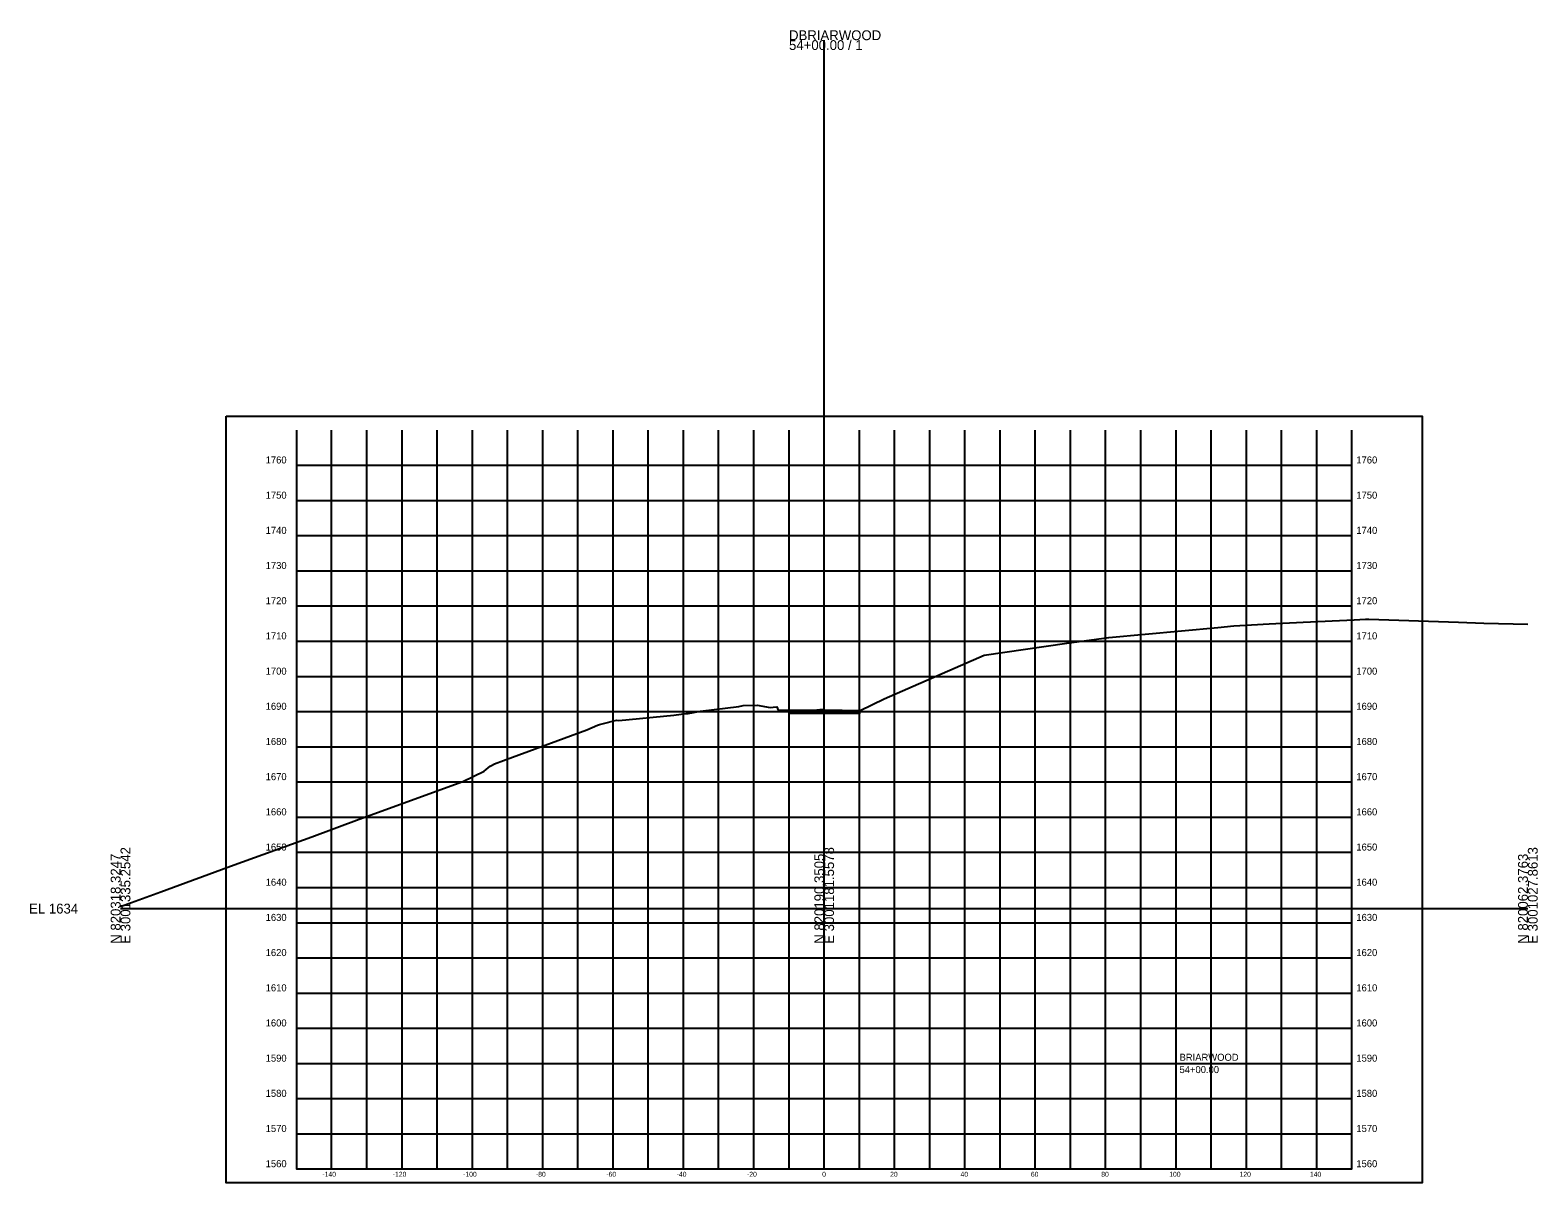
# Model space of a CAD drawing. Extents: x 74 to 503, y -54 to 3770.
# Drawn here: x 74.3 to 502.8, y 3442.1 to 3769.7 of the extents above; entities that cross this region are included whole.
import ezdxf

# ---------------------------------------------------------------- set-up
doc = ezdxf.new("R2010")
doc.units = 0
for name, color, linetype in [('DESIGN - EARTHWORK - Shapes', 7, 'Continuous'), ('DESIGN - SHEET - Corner Text', 7, 'Continuous'), ('DESIGN - SHEET - Light Grid', 7, 'Continuous'), ('DESIGN - SHEET - Linework', 7, 'Continuous'), ('DESIGN - SHEET - Plot Shape', 7, 'Continuous'), ('DESIGN - TYPICAL - Warning Text', 7, 'Continuous'), ('SURVEY - GROUND - Top of Ground', 7, 'Continuous')]:
    doc.layers.add(name, color=color, linetype=linetype)

msp = doc.modelspace()

# ---------------------------------------------------------------- linework, layer by layer
at = {"layer": 'DESIGN - EARTHWORK - Shapes'}
for points in [[(290, 3575.39), (290, 3576.39), (297.87, 3576.47), (298.74, 3576.48), (300, 3576.46), (310, 3576.32), (310, 3575.32), (300, 3575.46)], [(290, 3575.39), (290, 3576.39), (297.87, 3576.47), (298.74, 3576.48), (300, 3576.46), (310, 3576.32), (310, 3575.32), (300, 3575.46)], [(297.87, 3576.47), (298.74, 3576.48), (299.55, 3576.47), (300, 3576.46), (310, 3576.32), (310, 3575.32), (300, 3575.46), (290, 3575.39), (290, 3576.39)], [(298.74, 3576.48), (300, 3576.46), (299.55, 3576.47)], [(298.74, 3576.48), (300, 3576.46), (299.55, 3576.47)]]:
    msp.add_lwpolyline(points, close=True, dxfattribs=at)
at = {"layer": 'DESIGN - SHEET - Light Grid'}
for p, q in [((300, 3520), (300, 3766.81)), ((100, 3520), (300, 3520)), ((300, 3520), (500, 3520))]:
    msp.add_line(p, q, dxfattribs=at)
at = {"layer": 'DESIGN - SHEET - Linework'}
for p, q in [((160, 3446), (160, 3656)), ((170, 3446), (170, 3656)), ((180, 3446), (180, 3656)), ((190, 3446), (190, 3656)), ((200, 3446), (200, 3656)), ((210, 3446), (210, 3656)), ((220, 3446), (220, 3656)), ((230, 3446), (230, 3656)), ((240, 3446), (240, 3656)), ((250, 3446), (250, 3656)), ((260, 3446), (260, 3656)), ((270, 3446), (270, 3656)), ((280, 3446), (280, 3656)), ((290, 3446), (290, 3656)), ((300, 3446), (300, 3656)), ((310, 3446), (310, 3656)), ((320, 3446), (320, 3656)), ((330, 3446), (330, 3656)), ((340, 3446), (340, 3656)), ((350, 3446), (350, 3656)), ((360, 3446), (360, 3656)), ((370, 3446), (370, 3656)), ((380, 3446), (380, 3656)), ((390, 3446), (390, 3656)), ((400, 3446), (400, 3656)), ((410, 3446), (410, 3656)), ((420, 3446), (420, 3656)), ((430, 3446), (430, 3656)), ((440, 3446), (440, 3656)), ((150, 3646), (450, 3646)), ((150, 3636), (450, 3636)), ((150, 3626), (450, 3626)), ((150, 3616), (450, 3616)), ((150, 3606), (450, 3606)), ((150, 3596), (450, 3596)), ((150, 3586), (450, 3586)), ((150, 3576), (450, 3576)), ((150, 3566), (450, 3566)), ((150, 3556), (450, 3556)), ((150, 3546), (450, 3546)), ((150, 3536), (450, 3536)), ((150, 3526), (450, 3526)), ((150, 3516), (450, 3516)), ((150, 3506), (450, 3506)), ((150, 3496), (450, 3496)), ((150, 3486), (450, 3486)), ((150, 3476), (450, 3476)), ((150, 3466), (450, 3466)), ((150, 3456), (450, 3456))]:
    msp.add_line(p, q, dxfattribs=at)
msp.add_lwpolyline([(150, 3656), (150, 3446), (450, 3446), (450, 3656)], dxfattribs=at)
at = {"layer": 'DESIGN - SHEET - Plot Shape'}
msp.add_lwpolyline([(130, 3659.94), (470, 3659.94), (470, 3442.06), (130, 3442.06)], close=True, dxfattribs=at)
at = {"layer": 'SURVEY - GROUND - Top of Ground'}
msp.add_lwpolyline([(100, 3520.56), (111.49, 3524.81), (132.32, 3532.43), (154.41, 3540.44), (167.84, 3545.46), (197.33, 3556.12), (203.36, 3559.06), (205.06, 3560.5), (205.41, 3560.71), (206.25, 3561.1), (211.37, 3563.05), (232.5, 3570.84), (235.6, 3572.17), (236.14, 3572.32), (236.87, 3572.48), (240.97, 3573.51), (241.64, 3573.49), (257.25, 3575.02), (260.78, 3575.42), (261.37, 3575.45), (264.88, 3576.08), (275.7, 3577.42), (276.94, 3577.76), (280.9, 3577.86), (284.63, 3577.16), (285.49, 3577.22), (286.53, 3577.32), (286.96, 3576.37), (297.87, 3576.47), (298.74, 3576.48), (299.55, 3576.47), (300, 3576.46), (310.23, 3576.31), (317, 3579.66), (345.42, 3592.03), (368.99, 3595.47), (380.94, 3597.05), (411.9, 3599.93), (416.45, 3600.4), (426.44, 3600.96), (436.1, 3601.4), (450.64, 3602.08), (453.89, 3602.27), (454.83, 3602.21), (480.26, 3601.38), (487.49, 3601.14), (500, 3600.84)], dxfattribs=at)

# ---------------------------------------------------------------- texts
at = {"layer": 'DESIGN - SHEET - Corner Text'}
for s, height, p in [('1760', 2, (141.25, 3646.5)), ('1760', 2, (451.25, 3646.5)), ('1750', 2, (141.25, 3636.5)), ('1750', 2, (451.25, 3636.5)), ('1740', 2, (141.25, 3626.5)), ('1740', 2, (451.25, 3626.5)), ('1730', 2, (141.25, 3616.5)), ('1730', 2, (451.25, 3616.5)), ('1720', 2, (141.25, 3606.5)), ('1720', 2, (451.25, 3606.5)), ('1710', 2, (141.25, 3596.5)), ('1710', 2, (451.25, 3596.5)), ('1700', 2, (141.25, 3586.5)), ('1700', 2, (451.25, 3586.5)), ('1690', 2, (141.25, 3576.5)), ('1690', 2, (451.25, 3576.5)), ('1680', 2, (141.25, 3566.5)), ('1680', 2, (451.25, 3566.5)), ('1670', 2, (141.25, 3556.5)), ('1670', 2, (451.25, 3556.5)), ('1660', 2, (141.25, 3546.5)), ('1660', 2, (451.25, 3546.5)), ('1650', 2, (141.25, 3536.5)), ('1650', 2, (451.25, 3536.5)), ('1640', 2, (141.25, 3526.5)), ('1640', 2, (451.25, 3526.5)), ('1630', 2, (141.25, 3516.5)), ('1630', 2, (451.25, 3516.5)), ('1620', 2, (141.25, 3506.5)), ('1620', 2, (451.25, 3506.5)), ('1610', 2, (141.25, 3496.5)), ('1610', 2, (451.25, 3496.5)), ('1600', 2, (141.25, 3486.5)), ('1600', 2, (451.25, 3486.5)), ('1590', 2, (141.25, 3476.5)), ('1590', 2, (451.25, 3476.5)), ('1580', 2, (141.25, 3466.5)), ('1580', 2, (451.25, 3466.5)), ('1570', 2, (141.25, 3456.5)), ('1570', 2, (451.25, 3456.5)), ('1560', 2, (141.25, 3446.5)), ('1560', 2, (451.25, 3446.5)), ('-140', 1.4, (157.37, 3443.8)), ('-120', 1.4, (177.37, 3443.8)), ('-100', 1.4, (197.37, 3443.8)), ('-80', 1.4, (218.06, 3443.8)), ('-60', 1.4, (238.06, 3443.8)), ('-40', 1.4, (258.06, 3443.8)), ('-20', 1.4, (278.06, 3443.8)), ('0', 1.4, (299.42, 3443.8)), ('20', 1.4, (318.74, 3443.8)), ('40', 1.4, (338.74, 3443.8)), ('60', 1.4, (358.74, 3443.8)), ('80', 1.4, (378.74, 3443.8)), ('100', 1.4, (398.06, 3443.8)), ('120', 1.4, (418.06, 3443.8)), ('140', 1.4, (438.06, 3443.8))]:
    msp.add_text(s, height=height, dxfattribs=at).set_placement(p)
at = {"layer": 'DESIGN - SHEET - Light Grid'}
for s, p in [('54+00.00 / 1', (290, 3764.01)), ('DBRIARWOOD', (290, 3766.81)), ('EL 1634', (74, 3518.6))]:
    msp.add_text(s, height=2.8, dxfattribs=at).set_placement(p)
for s, p in [('N 820318.3247', (100, 3510)), ('E 3001335.2542', (102.8, 3510)), ('N 820190.3505', (300, 3510)), ('E 3001181.5578', (302.8, 3510)), ('N 820062.3763', (500, 3510)), ('E 3001027.8613', (502.8, 3510))]:
    msp.add_text(s, height=2.8, rotation=90, dxfattribs=at).set_placement(p)
at = {"layer": 'DESIGN - TYPICAL - Warning Text'}
for s, p in [('BRIARWOOD', (401, 3476.75)), ('54+00.00', (401, 3473.25))]:
    msp.add_text(s, height=2, dxfattribs=at).set_placement(p)

doc.saveas('drawing.dxf')
